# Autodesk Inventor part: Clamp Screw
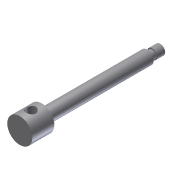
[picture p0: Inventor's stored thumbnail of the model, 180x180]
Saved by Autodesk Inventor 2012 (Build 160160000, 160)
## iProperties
Shininess: 77.0
Length Units: 11269
Angle Units: 11279
Time Units: 11290
Mass Units: 11283
Length Display Precision: 3
Angle Display Precision: 2
Created: 2002-02
Part Number: Clamp Screw
Document SubType Name: Modeling
Designer: ***
Density: 1 g/cm^3
Material: Default
Density: 0.0
Volumn: 0.0
Area: 0.0
PropertySet Name: Model Information
Control State: 0
Master: False
Checked Out: False
Author: ***
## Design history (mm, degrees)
sketch "Sketch1"
  geometry: L1 (0, 140)-(5, 140); L2 (5, 140)-(5, 132); L3 (5, 132)-(4, 132); L4 (4, 132)-(4, 127); L5 (4, 127)-(6.5, 127); L6 (6.5, 127)-(6.5, 25); L7 (6.5, 25)-(4, 25); L8 (4, 25)-(4, 22); L9 (4, 22)-(12.5, 22); L10 (12.5, 22)-(12.5, 0); L11 (12.5, 0)-(0, 0); L12 (0, 0)-(0, 140)
  constraints: 24 end point, 10 parallel, 1 horizontal, 1 perpendicular
  dimensions: "d0" = 10 diameter of L2 L12; "d1" = 8 diameter of L4 L12; "d2" = 13 diameter of L6 L12; "d3" = 8 diameter of L7.end L12; "d4" = 25 diameter of L10 L12; "d5" = 3 distance from line of L7.end L9; "d6" = 8 distance of L1.end L2.end; "d7" = 13 vertical distance of L1.end L5.end; "d8" = 22 distance of L9.end L10.end; "d10" = 102 distance of L5.end L6.end
revolve "Revolution1" sketch "Sketch1" stored, may be unused: angle "d11" = 90 deg
sketch "Sketch3"
  geometry: L1 (-12.5, 0)-(12.5, 0) reference; C1 r 5 at (-0.113, 11)
  constraints: 1 centre point
  dimensions: "d13" = 10 diameter of C1; "d14" = 11 distance from line of L1 C1.centre
extrude "Extrusion1" cut sketch "Sketch3" stored distance "d15" = 10; taper "d16" = 0 deg
body "Solid1"
